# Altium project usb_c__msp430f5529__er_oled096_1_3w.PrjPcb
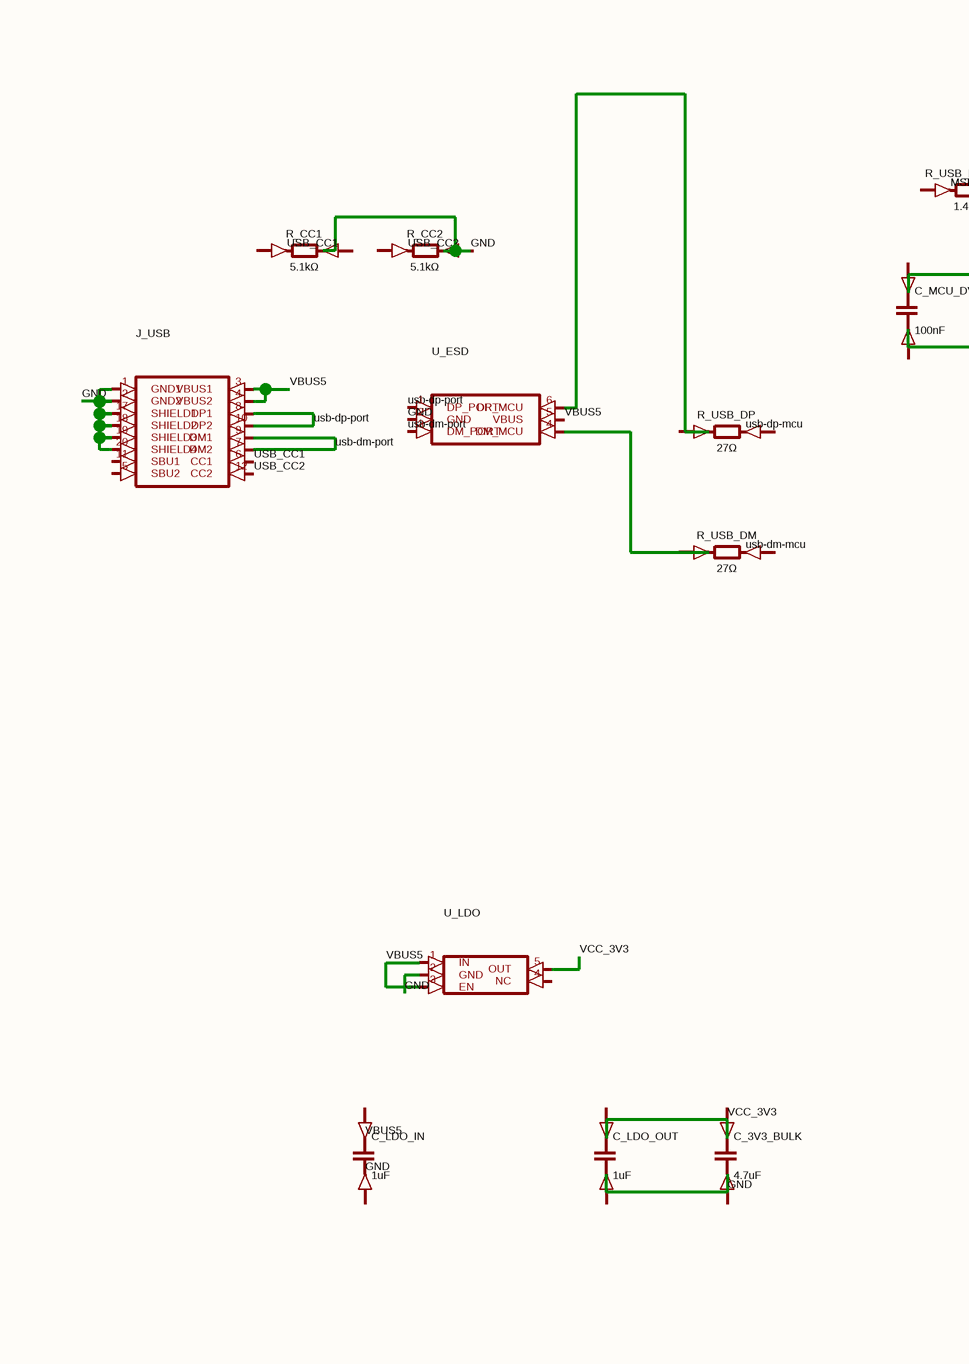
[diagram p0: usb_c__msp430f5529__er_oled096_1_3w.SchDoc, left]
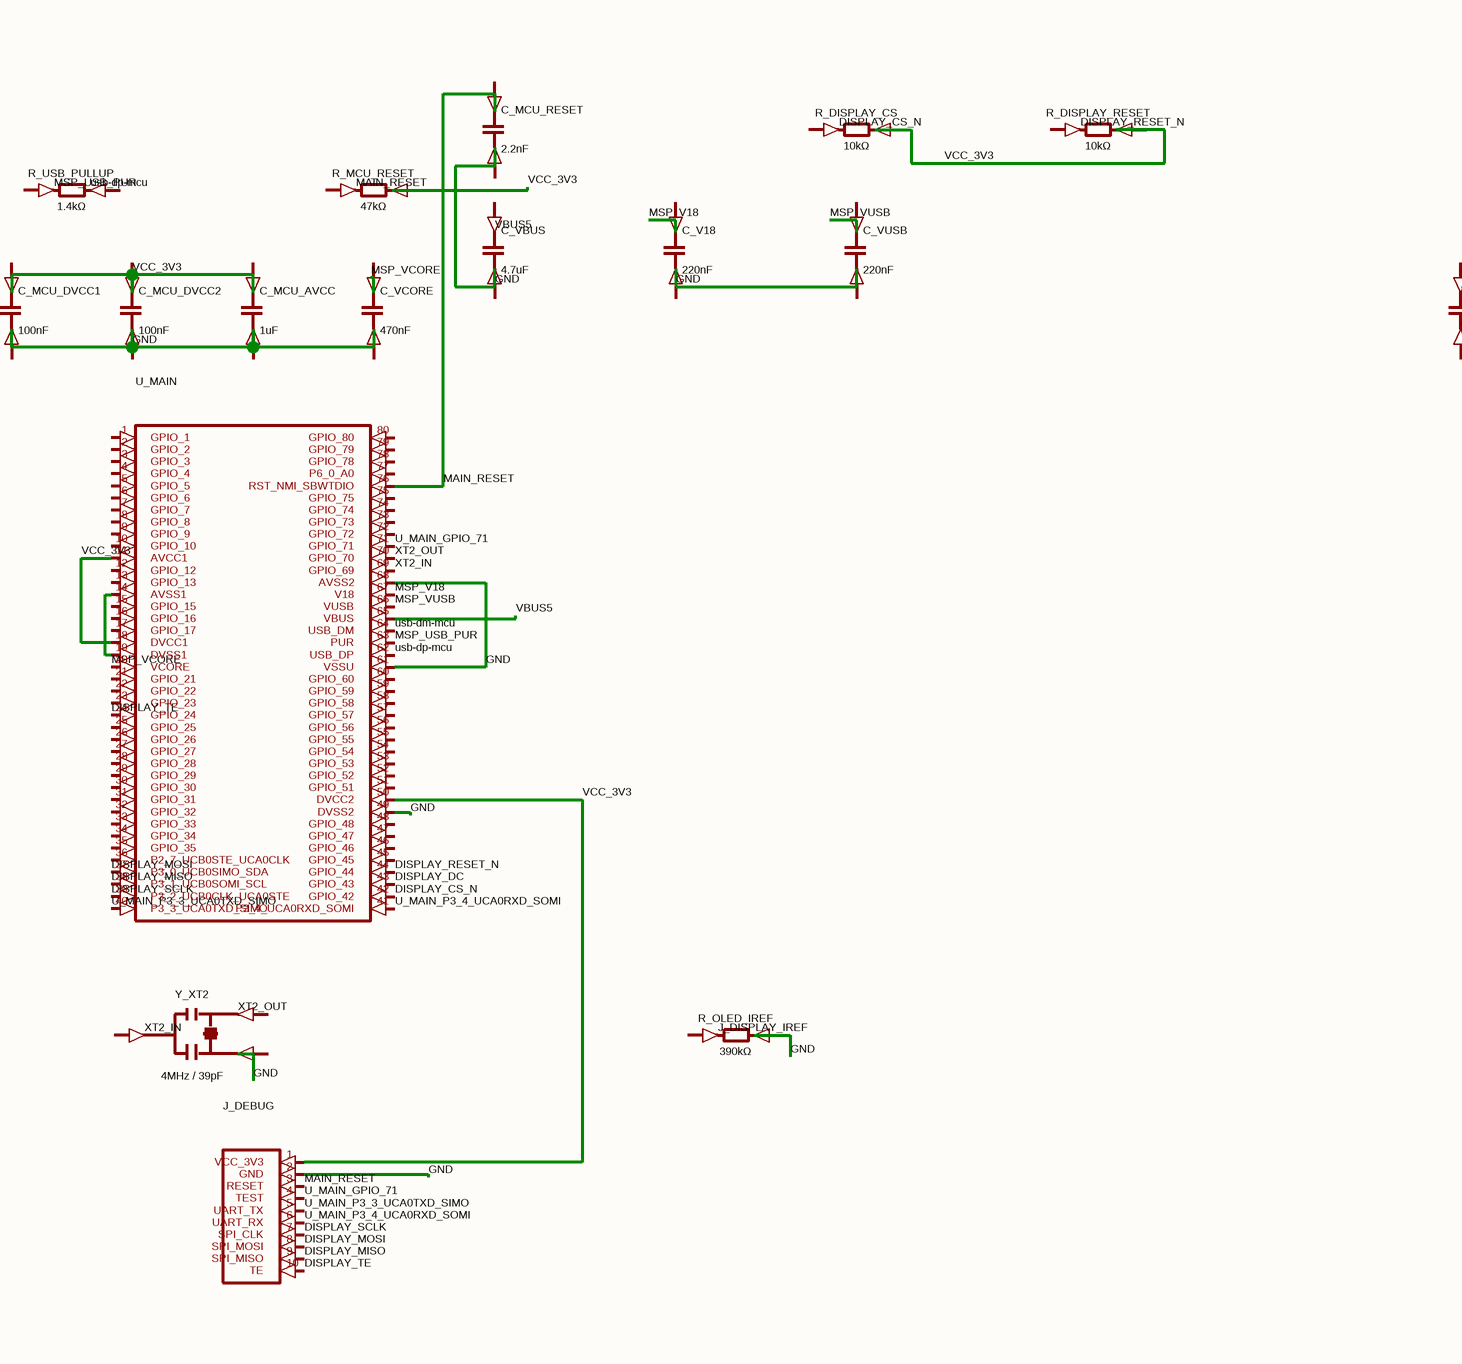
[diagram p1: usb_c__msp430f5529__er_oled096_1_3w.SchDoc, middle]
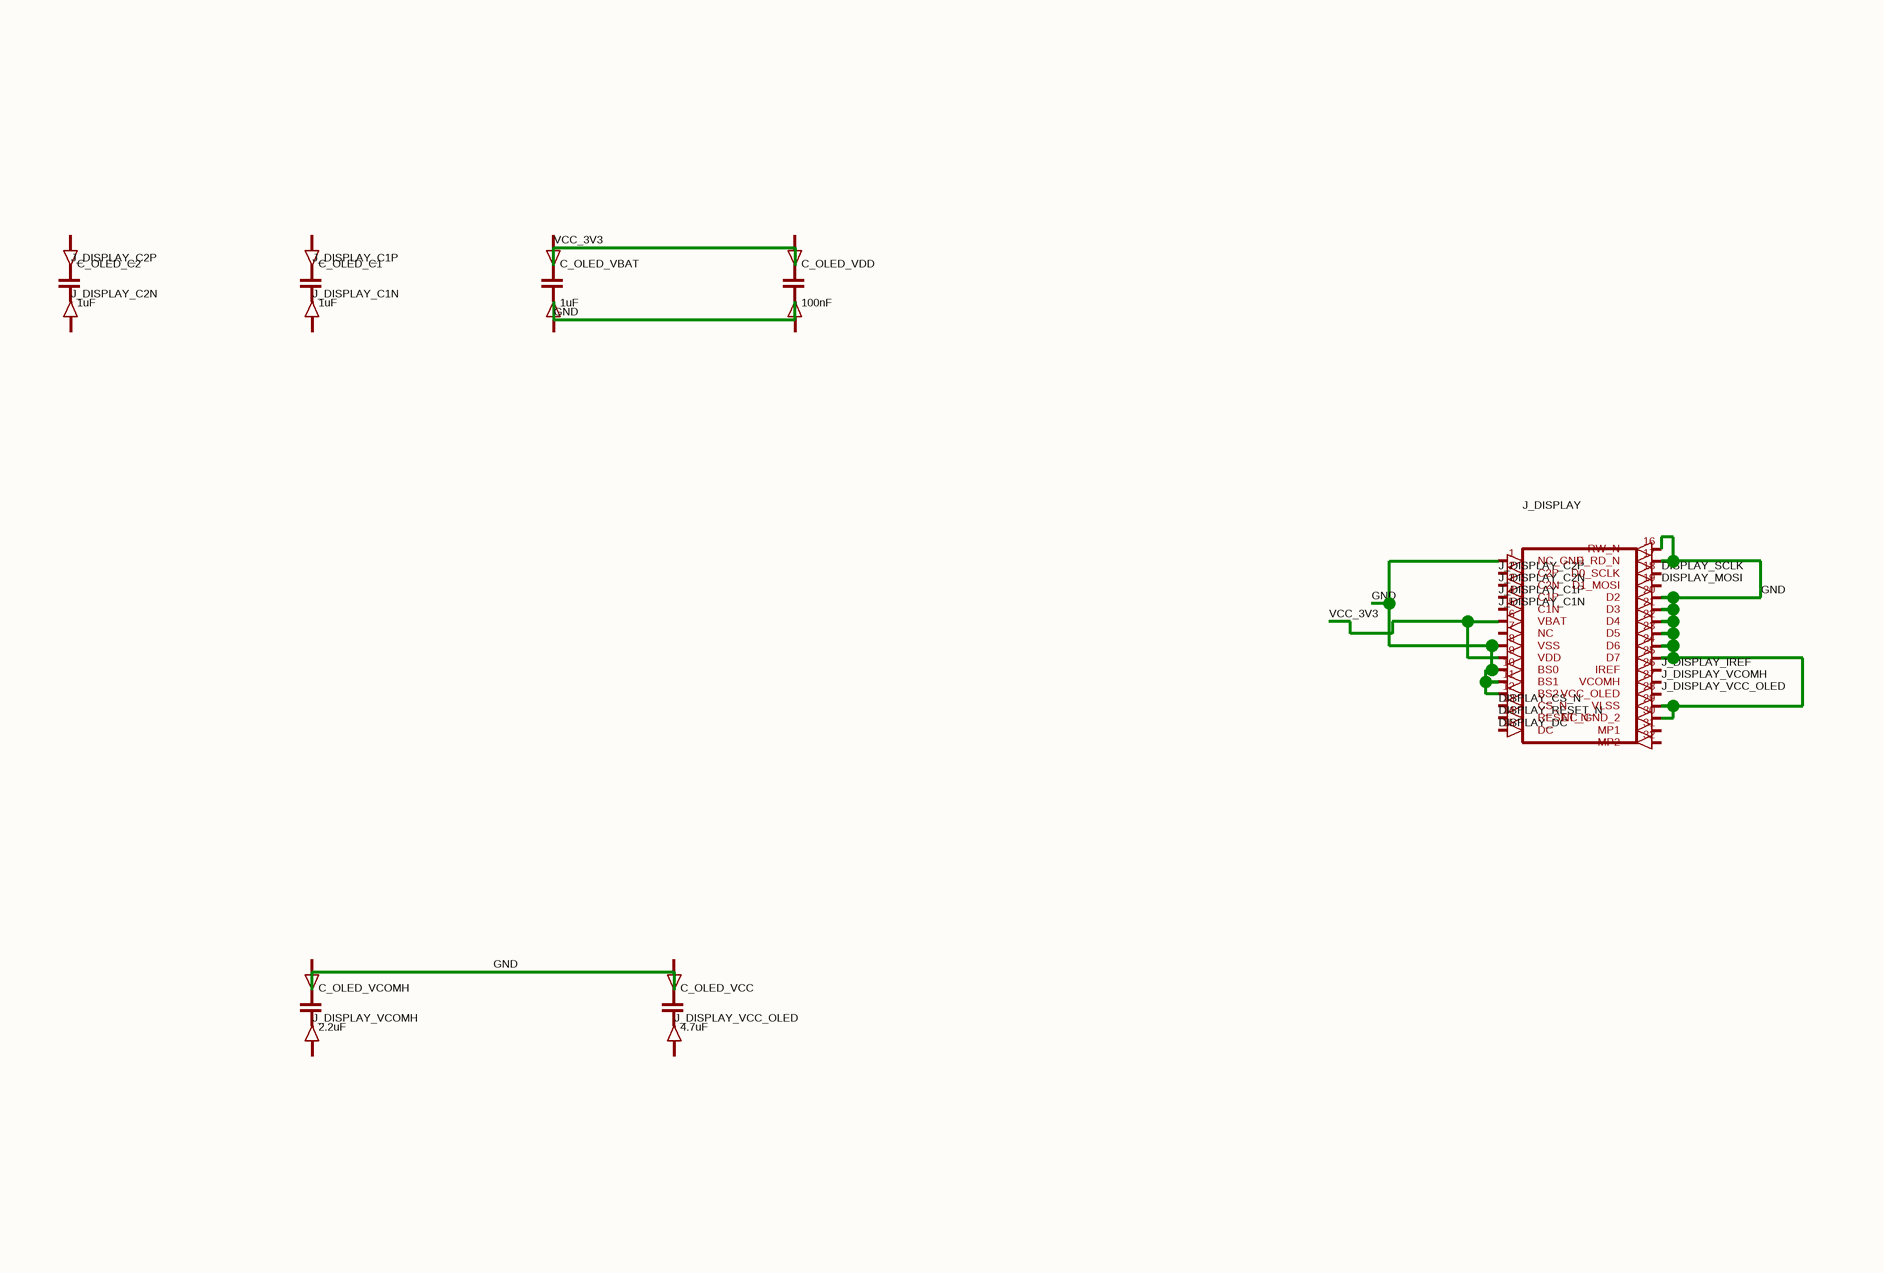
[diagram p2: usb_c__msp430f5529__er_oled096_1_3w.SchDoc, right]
1 sheet, 33 parts. Net scope: global (net labels, ports and power ports of the same name join across sheets).
Board file: usb_c__msp430f5529__er_oled096_1_3w.PcbDoc

## Sheet usb_c__msp430f5529__er_oled096_1_3w.SchDoc
size 388 x 149 mm

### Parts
C_3V3_BULK  4.7uF
C_LDO_IN  1uF
C_LDO_OUT  1uF
C_MCU_AVCC  1uF
C_MCU_DVCC1  100nF
C_MCU_DVCC2  100nF
C_MCU_RESET  2.2nF
C_OLED_C1  1uF
C_OLED_C2  1uF
C_OLED_VBAT  1uF
C_OLED_VCC  4.7uF
C_OLED_VCOMH  2.2uF
C_OLED_VDD  100nF
C_V18  220nF
C_VBUS  4.7uF
C_VCORE  470nF
C_VUSB  220nF
J_DEBUG  (no value)
J_DISPLAY  (no value)
J_USB  (no value)
R_CC1  5.1kΩ
R_CC2  5.1kΩ
R_DISPLAY_CS  10kΩ
R_DISPLAY_RESET  10kΩ
R_MCU_RESET  47kΩ
R_OLED_IREF  390kΩ
R_USB_DM  27Ω
R_USB_DP  27Ω
R_USB_PULLUP  1.4kΩ
U_ESD  (no value)
U_LDO  (no value)
U_MAIN  (no value)
Y_XT2  4MHz / 39pF

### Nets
DISPLAY_CS_N: J_DISPLAY.13(CS_N) U_MAIN.42(GPIO_42)
DISPLAY_DC: J_DISPLAY.15(DC) U_MAIN.43(GPIO_43)
DISPLAY_MISO: J_DEBUG.9(SPI_MISO) U_MAIN.38(P3_1_UCB0SOMI_SCL)
DISPLAY_MOSI: J_DEBUG.8(SPI_MOSI) J_DISPLAY.19(D1_MOSI) U_MAIN.37(P3_0_UCB0SIMO_SDA)
DISPLAY_RESET_N: J_DISPLAY.14(RESET_N) U_MAIN.44(GPIO_44)
DISPLAY_SCLK: J_DEBUG.7(SPI_CLK) J_DISPLAY.18(D0_SCLK) U_MAIN.39(P3_2_UCB0CLK_UCA0STE)
DISPLAY_TE: J_DEBUG.10(TE) U_MAIN.24(GPIO_24)
GND: J_DEBUG.1(VCC_3V3) J_DEBUG.2(GND) J_DISPLAY.1(NC_GND) J_DISPLAY.6(VBAT) J_DISPLAY.8(VSS) J_DISPLAY.9(VDD) J_DISPLAY.10(BS0) J_DISPLAY.11(BS1) J_DISPLAY.12(BS2) J_DISPLAY.16(RW_N) J_DISPLAY.17(E_RD_N) J_DISPLAY.20(D2) J_DISPLAY.21(D3) J_DISPLAY.22(D4) J_DISPLAY.23(D5) J_DISPLAY.24(D6) J_DISPLAY.25(D7) J_DISPLAY.29(VLSS) J_DISPLAY.30(NC_GND_2) J_USB.1(GND1) J_USB.2(GND2) J_USB.3(VBUS1) J_USB.4(VBUS2) J_USB.17(SHIELD1) J_USB.18(SHIELD2) J_USB.19(SHIELD3) J_USB.20(SHIELD4) R_DISPLAY_CS.2(cathode) R_DISPLAY_RESET.2(cathode) R_MCU_RESET.2(cathode) R_OLED_IREF.2(cathode) U_ESD.2(GND) U_ESD.5(VBUS) U_LDO.1(IN) U_LDO.2(GND) U_LDO.3(EN) U_LDO.5(OUT) U_MAIN.11(AVCC1) U_MAIN.14(AVSS1) U_MAIN.18(DVCC1) U_MAIN.19(DVSS1) U_MAIN.49(DVSS2) U_MAIN.50(DVCC2) U_MAIN.61(VSSU) U_MAIN.65(VBUS) U_MAIN.68(AVSS2)  [also labelled VBUS5, VCC_3V3]
J_DISPLAY_C1N: J_DISPLAY.5(C1N)
J_DISPLAY_C1P: J_DISPLAY.4(C1P)
J_DISPLAY_C2N: J_DISPLAY.3(C2N)
J_DISPLAY_C2P: J_DISPLAY.2(C2P)
J_DISPLAY_IREF: J_DISPLAY.26(IREF)
J_DISPLAY_VCC_OLED: J_DISPLAY.28(VCC_OLED)
J_DISPLAY_VCOMH: J_DISPLAY.27(VCOMH)
MAIN_RESET: J_DEBUG.3(RESET) U_MAIN.76(RST_NMI_SBWTDIO)
MSP_USB_PUR: U_MAIN.63(PUR)
MSP_V18: U_MAIN.67(V18)
MSP_VCORE: U_MAIN.20(VCORE)
MSP_VUSB: U_MAIN.66(VUSB)
U_MAIN_GPIO_71: J_DEBUG.4(TEST) U_MAIN.71(GPIO_71)
U_MAIN_P3_3_UCA0TXD_SIMO: J_DEBUG.5(UART_TX) U_MAIN.40(P3_3_UCA0TXD_SIMO)
U_MAIN_P3_4_UCA0RXD_SOMI: J_DEBUG.6(UART_RX) U_MAIN.41(P3_4_UCA0RXD_SOMI)
usb-dm-mcu: U_MAIN.64(USB_DM)
usb-dm-port: J_USB.7(DM2) J_USB.9(DM1) U_ESD.3(DM_PORT)
usb-dp-mcu: U_MAIN.62(USB_DP)
usb-dp-port: J_USB.8(DP1) J_USB.10(DP2) U_ESD.1(DP_PORT)
USB_CC1: J_USB.6(CC1)
USB_CC2: J_USB.12(CC2)
XT2_IN: U_MAIN.69(GPIO_69)
XT2_OUT: U_MAIN.70(GPIO_70)
NetR_USB_DM_1: R_USB_DM.1(anode) U_ESD.4(DM_MCU)

Not connected (* = marked no-connect by the designer): C_3V3_BULK 1(anode) 2(cathode); C_LDO_IN 1(anode) 2(cathode); C_LDO_OUT 1(anode) 2(cathode); C_MCU_AVCC 1(anode) 2(cathode); C_MCU_DVCC1 1(anode) 2(cathode); C_MCU_DVCC2 1(anode) 2(cathode); C_MCU_RESET 1(anode) 2(cathode); C_OLED_C1 1(anode) 2(cathode); C_OLED_C2 1(anode) 2(cathode); C_OLED_VBAT 1(anode) 2(cathode); C_OLED_VCC 1(anode) 2(cathode); C_OLED_VCOMH 1(anode) 2(cathode); C_OLED_VDD 1(anode) 2(cathode); C_V18 1(anode) 2(cathode); C_VBUS 1(anode) 2(cathode); C_VCORE 1(anode) 2(cathode); C_VUSB 1(anode) 2(cathode); J_DISPLAY 7(NC) 31(MP1) 32(MP2); J_USB 5(SBU2) 11(SBU1); R_CC1 1(anode) 2(cathode); R_CC2 1(anode) 2(cathode); R_DISPLAY_CS 1(anode); R_DISPLAY_RESET 1(anode); R_MCU_RESET 1(anode); R_OLED_IREF 1(anode); R_USB_DM 2(cathode); R_USB_DP 1(anode) 2(cathode); R_USB_PULLUP 1(anode) 2(cathode); U_ESD 6(DP_MCU); U_LDO 4(NC); U_MAIN 1(GPIO_1) 2(GPIO_2) 3(GPIO_3) 4(GPIO_4) 5(GPIO_5) 6(GPIO_6) 7(GPIO_7) 8(GPIO_8) 9(GPIO_9) 10(GPIO_10) 12(GPIO_12) 13(GPIO_13) 15(GPIO_15) 16(GPIO_16) 17(GPIO_17) 21(GPIO_21) 22(GPIO_22) 23(GPIO_23) 25(GPIO_25) 26(GPIO_26) 27(GPIO_27) 28(GPIO_28) 29(GPIO_29) 30(GPIO_30) 31(GPIO_31) 32(GPIO_32) 33(GPIO_33) 34(GPIO_34) 35(GPIO_35) 36(P2_7_UCB0STE_UCA0CLK) 45(GPIO_45) 46(GPIO_46) 47(GPIO_47) 48(GPIO_48) 51(GPIO_51) 52(GPIO_52) 53(GPIO_53) 54(GPIO_54) 55(GPIO_55) 56(GPIO_56) 57(GPIO_57) 58(GPIO_58) 59(GPIO_59) 60(GPIO_60) 72(GPIO_72) 73(GPIO_73) 74(GPIO_74) 75(GPIO_75) 77(P6_0_A0) 78(GPIO_78) 79(GPIO_79) 80(GPIO_80); Y_XT2 1(pin1) 2(pin2) 3(pin3)

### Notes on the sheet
- Labels drawn without touching a wire or pin: DISPLAY_CS_N, DISPLAY_RESET_N, GND, J_DISPLAY_C1N, J_DISPLAY_C1P, J_DISPLAY_C2N, J_DISPLAY_C2P, J_DISPLAY_IREF, J_DISPLAY_VCC_OLED, J_DISPLAY_VCOMH, MAIN_RESET, MSP_USB_PUR, usb-dm-mcu, usb-dp-mcu, USB_CC1, USB_CC2, VBUS5, XT2_IN, XT2_OUT

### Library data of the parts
C_3V3_BULK C_LDO_IN C_LDO_OUT C_MCU_AVCC C_MCU_DVCC1 C_MCU_DVCC2 C_MCU_RESET C_OLED_C1 C_OLED_C2 C_OLED_VBAT C_OLED_VCC C_OLED_VCOMH C_OLED_VDD C_V18 C_VBUS C_VCORE C_VUSB = capacitor_down
J_DEBUG = J_DEBUG
J_DISPLAY = J_DISPLAY
J_USB = J_USB
R_CC1 R_CC2 R_DISPLAY_CS R_DISPLAY_RESET R_MCU_RESET R_OLED_IREF R_USB_DM R_USB_DP R_USB_PULLUP = boxresistor_right
U_ESD = U_ESD
U_LDO = U_LDO
U_MAIN = U_MAIN
Y_XT2 = resonator_right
